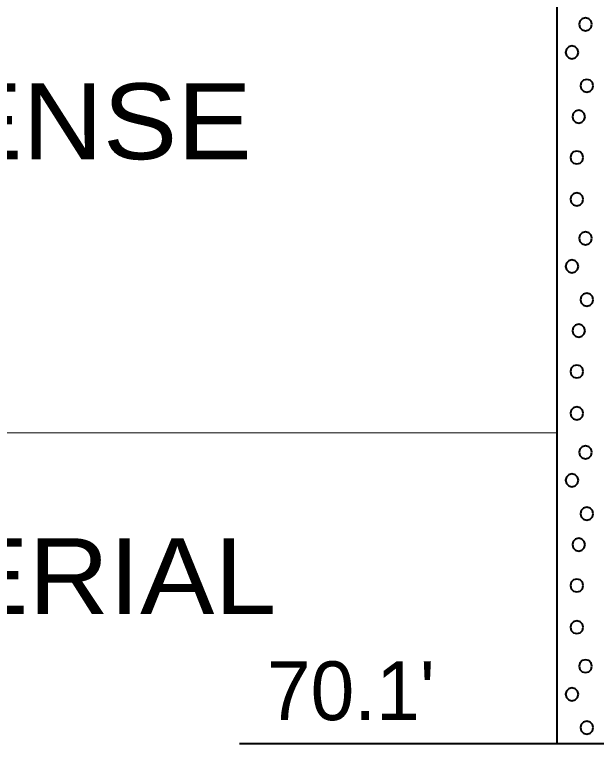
# Model space of a CAD drawing. Extents: x -76 to 974, y -1080 to -735.
# Drawn here: x 922.57 to 929.48, y -995.78 to -987.13 of the extents above; entities that cross this region are included whole.
import ezdxf
from ezdxf.enums import TextEntityAlignment as Align

# ---------------------------------------------------------------- set-up
doc = ezdxf.new("R2010")
doc.units = 0
doc.header["$LTSCALE"] = 0.36
doc.layers.add('27', color=7, linetype='Continuous', lineweight=40)
doc.layers.add('7', color=7, linetype='Continuous', lineweight=13)
doc.layers.add('29', color=7, linetype='Continuous')

msp = doc.modelspace()

# ---------------------------------------------------------------- linework, layer by layer
at = {"layer": '27'}
for p, q in [((929.0077, -982.6789), (929.0077, -995.7789)), ((925.2403, -995.7789), (929.0077, -995.7789)), ((929.0077, -995.7789), (931.5077, -995.7789))]:
    msp.add_line(p, q, dxfattribs=at)
for points in [[(929.4235, -987.2423), (929.4133, -987.2042), (929.3854, -987.1763), (929.3473, -987.1661), (929.3092, -987.1763), (929.2814, -987.2042), (929.2711, -987.2423), (929.2814, -987.2804), (929.3092, -987.3083), (929.3473, -987.3185), (929.3854, -987.3083), (929.4133, -987.2804)], [(929.2621, -987.5754), (929.2519, -987.5373), (929.224, -987.5094), (929.1859, -987.4992), (929.1478, -987.5094), (929.1199, -987.5373), (929.1097, -987.5754), (929.1199, -987.6135), (929.1478, -987.6414), (929.1859, -987.6516), (929.224, -987.6414), (929.2519, -987.6135)], [(929.4396, -987.9716), (929.4294, -987.9335), (929.4015, -987.9056), (929.3634, -987.8954), (929.3253, -987.9056), (929.2974, -987.9335), (929.2872, -987.9716), (929.2974, -988.0097), (929.3253, -988.0375), (929.3634, -988.0478), (929.4015, -988.0375), (929.4294, -988.0097)], [(929.3435, -988.3394), (929.3332, -988.3013), (929.3054, -988.2734), (929.2673, -988.2632), (929.2292, -988.2734), (929.2013, -988.3013), (929.1911, -988.3394), (929.2013, -988.3775), (929.2292, -988.4054), (929.2673, -988.4156), (929.3054, -988.4054), (929.3332, -988.3775)], [(929.3206, -988.8238), (929.3104, -988.7857), (929.2825, -988.7578), (929.2444, -988.7476), (929.2063, -988.7578), (929.1784, -988.7857), (929.1682, -988.8238), (929.1784, -988.8619), (929.2063, -988.8897), (929.2444, -988.9), (929.2825, -988.8897), (929.3104, -988.8619)], [(929.3206, -989.3196), (929.3104, -989.2815), (929.2825, -989.2536), (929.2444, -989.2434), (929.2063, -989.2536), (929.1784, -989.2815), (929.1682, -989.3196), (929.1784, -989.3577), (929.2063, -989.3855), (929.2444, -989.3958), (929.2825, -989.3855), (929.3104, -989.3577)], [(929.4235, -989.7823), (929.4133, -989.7442), (929.3854, -989.7163), (929.3473, -989.7061), (929.3092, -989.7163), (929.2814, -989.7442), (929.2711, -989.7823), (929.2814, -989.8204), (929.3092, -989.8483), (929.3473, -989.8585), (929.3854, -989.8483), (929.4133, -989.8204)], [(929.2621, -990.1154), (929.2519, -990.0773), (929.224, -990.0494), (929.1859, -990.0392), (929.1478, -990.0494), (929.1199, -990.0773), (929.1097, -990.1154), (929.1199, -990.1535), (929.1478, -990.1814), (929.1859, -990.1916), (929.224, -990.1814), (929.2519, -990.1535)], [(929.4396, -990.5116), (929.4294, -990.4735), (929.4015, -990.4456), (929.3634, -990.4354), (929.3253, -990.4456), (929.2974, -990.4735), (929.2872, -990.5116), (929.2974, -990.5497), (929.3253, -990.5775), (929.3634, -990.5878), (929.4015, -990.5775), (929.4294, -990.5497)], [(929.3435, -990.8794), (929.3332, -990.8413), (929.3054, -990.8134), (929.2673, -990.8032), (929.2292, -990.8134), (929.2013, -990.8413), (929.1911, -990.8794), (929.2013, -990.9175), (929.2292, -990.9454), (929.2673, -990.9556), (929.3054, -990.9454), (929.3332, -990.9175)], [(929.3206, -991.3638), (929.3104, -991.3257), (929.2825, -991.2978), (929.2444, -991.2876), (929.2063, -991.2978), (929.1784, -991.3257), (929.1682, -991.3638), (929.1784, -991.4019), (929.2063, -991.4297), (929.2444, -991.44), (929.2825, -991.4297), (929.3104, -991.4019)], [(929.3206, -991.8596), (929.3104, -991.8215), (929.2825, -991.7936), (929.2444, -991.7834), (929.2063, -991.7936), (929.1784, -991.8215), (929.1682, -991.8596), (929.1784, -991.8977), (929.2063, -991.9255), (929.2444, -991.9358), (929.2825, -991.9255), (929.3104, -991.8977)], [(929.4235, -992.3223), (929.4133, -992.2842), (929.3854, -992.2563), (929.3473, -992.2461), (929.3092, -992.2563), (929.2814, -992.2842), (929.2711, -992.3223), (929.2814, -992.3604), (929.3092, -992.3883), (929.3473, -992.3985), (929.3854, -992.3883), (929.4133, -992.3604)], [(929.2621, -992.6554), (929.2519, -992.6173), (929.224, -992.5894), (929.1859, -992.5792), (929.1478, -992.5894), (929.1199, -992.6173), (929.1097, -992.6554), (929.1199, -992.6935), (929.1478, -992.7214), (929.1859, -992.7316), (929.224, -992.7214), (929.2519, -992.6935)], [(929.4396, -993.0516), (929.4294, -993.0135), (929.4015, -992.9856), (929.3634, -992.9754), (929.3253, -992.9856), (929.2974, -993.0135), (929.2872, -993.0516), (929.2974, -993.0897), (929.3253, -993.1175), (929.3634, -993.1278), (929.4015, -993.1175), (929.4294, -993.0897)], [(929.3435, -993.4194), (929.3332, -993.3813), (929.3054, -993.3534), (929.2673, -993.3432), (929.2292, -993.3534), (929.2013, -993.3813), (929.1911, -993.4194), (929.2013, -993.4575), (929.2292, -993.4854), (929.2673, -993.4956), (929.3054, -993.4854), (929.3332, -993.4575)], [(929.3206, -993.9038), (929.3104, -993.8657), (929.2825, -993.8378), (929.2444, -993.8276), (929.2063, -993.8378), (929.1784, -993.8657), (929.1682, -993.9038), (929.1784, -993.9419), (929.2063, -993.9697), (929.2444, -993.98), (929.2825, -993.9697), (929.3104, -993.9419)], [(929.3206, -994.3996), (929.3104, -994.3615), (929.2825, -994.3336), (929.2444, -994.3234), (929.2063, -994.3336), (929.1784, -994.3615), (929.1682, -994.3996), (929.1784, -994.4377), (929.2063, -994.4655), (929.2444, -994.4758), (929.2825, -994.4655), (929.3104, -994.4377)], [(929.4235, -994.8623), (929.4133, -994.8242), (929.3854, -994.7963), (929.3473, -994.7861), (929.3092, -994.7963), (929.2814, -994.8242), (929.2711, -994.8623), (929.2814, -994.9004), (929.3092, -994.9283), (929.3473, -994.9385), (929.3854, -994.9283), (929.4133, -994.9004)], [(929.2621, -995.1954), (929.2519, -995.1573), (929.224, -995.1294), (929.1859, -995.1192), (929.1478, -995.1294), (929.1199, -995.1573), (929.1097, -995.1954), (929.1199, -995.2335), (929.1478, -995.2614), (929.1859, -995.2716), (929.224, -995.2614), (929.2519, -995.2335)], [(929.4396, -995.5916), (929.4294, -995.5535), (929.4015, -995.5256), (929.3634, -995.5154), (929.3253, -995.5256), (929.2974, -995.5535), (929.2872, -995.5916), (929.2974, -995.6297), (929.3253, -995.6575), (929.3634, -995.6678), (929.4015, -995.6575), (929.4294, -995.6297)]]:
    msp.add_lwpolyline(points, close=True, dxfattribs=at)
at = {"layer": '7'}
msp.add_line((903.0224, -992.09), (929.0077, -992.09), dxfattribs=at)

# ---------------------------------------------------------------- texts
at = {"layer": '27'}
msp.add_text("70.1'", height=0.6976, dxfattribs=at).set_placement((925.5643, -995.5025))
at = {"layer": '29', "width": 1.1}
for s, p in [('MEDIUM DENSE TO VERY DENSE', (914.6807, -988.8435)), ('WITH TRACE OF SHELL MATERIAL', (914.6806, -994.2435))]:
    msp.add_text(s, height=0.9, dxfattribs=at).set_placement(p, align=Align.CENTER)

doc.saveas('drawing.dxf')
